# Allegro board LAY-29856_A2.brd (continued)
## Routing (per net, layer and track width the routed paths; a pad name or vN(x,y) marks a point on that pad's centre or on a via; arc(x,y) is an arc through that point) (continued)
P3V3_SDA: length 105.7
  TOP w0.152: v1(136.65,54.86) 136.49,55.02 U23.1 ; U24.1 136.49,50.32 v1(136.65,50.16) ; U21.1 136.49,64.42 v1(136.65,64.26)
  TOP w0.203: v1(136.64,58.88) 136.48,59.04 U22.1 ; U15.1 117.86,63.12 C153.1
  TOP w0.279: C154.1 124.33,68.83 U17.5 ; U16.11 119.77,76.82 v1(119.44,77.15) ; v1(121.41,79.5) 121.69,79.23 U16.7
  TOP w0.305: 125.79,78.98 125.55,78.74 124.84,78.74 124.69,78.59 U16.1
  TOP w0.381: J29.1 C163.1 105.92,87.63 106.3,88.01 112.39,88.01 112.77,87.63 R207.1 116.83,82.42 ; v1(125.98,68.07) 126.87,67.18 135,67.18 v1(135.64,66.55) ; v1(125.98,68.07) v1(125.98,70.48) ; v1(125.98,68.07) C154.1 ; v1(136.65,64.26) 136.65,64.14 R194.1 ; C156.1 121.41,79.51 v1(121.41,79.5) ; C153.1 117.35,61.59 R180.1 117.35,60.07 117.86,59.56 120.65,59.56 121.54,60.45 121.54,62.1 122.05,62.1 122.43,62.48 122.43,66.68 v1(122.18,66.93) R185.1 ; R206.1 v1(137.03,47.75) ; 116.83,82.42 C155.1 v1(120.4,82.42) 120.52,82.42 R181.1 ; 116.83,82.42 116.83,79.76 v1(119.44,77.15) ; v1(117.22,75.95) 116.72,75.44 R182.1 ; R209.1 132.59,77.72 v1(132.59,77.72) ; R202.1 v1(137.03,52.45) ; 127.64,75.69 v1(127.64,74.68) ; 125.79,78.98 126.24,79.43 v1(126.24,80.26) C157.1
  BOTTOM w0.381: v1(135.64,66.55) 135.64,65.28 v1(136.65,64.26) 137.92,62.99 137.92,60.16 v1(136.64,58.88) 136.65,58.87 v1(136.65,54.86) 136.65,52.83 v1(137.03,52.45) 136.65,52.07 v1(136.65,50.16) 137.03,49.78 v1(137.03,47.75) ; v1(122.18,66.93) 124.84,66.93 v1(125.98,68.07) ; v1(119.44,77.15) 118.43,77.15 v1(117.22,75.95)
P5V0_SDA_USB_CONN_VBUS: length 6.2
  TOP w0.381: L11.1 127.24,81.97 U18.1 127.24,83.96 126.75,84.45 124.84,84.45 124.49,84.81 J23.1
P5V_SDA: length 51.8
  TOP w0.254: U25.B2 U25.B1 U25.C1
  TOP w0.279: U16.6 122.19,79.49 v1(122.17,79.5)
  TOP w0.381: R212.1 C164.1 ; 130.05,81.03 130.43,80.64 131.44,80.64 133.22,78.87 v1(133.22,78.49) ; 130.05,81.03 129.67,80.64 127.76,80.64 v1(127,79.88) ; 130.05,81.03 C159.1 L11.2 ; v1(128.14,78.87) 128.26,78.99 R200.1 ; R195.1 116.2,67.44 114.55,69.09 114.55,72.9 113.46,73.99 113.46,78.79 v1(113.54,78.87) ; R208.1 132.46,72.64
  BOTTOM w0.381: v1(128.14,78.87) 128.02,78.87 v1(127,79.88) 125.73,78.61 123.7,78.61 122.81,79.5 v1(122.17,79.5) 122.17,79.25 121.79,78.87 v1(113.54,78.87) ; v1(133.22,78.49) 133.22,77.09 132.33,76.2 v1(132.33,74.3)
P5V_SDA_S: length 172.2
  TOP w0.381: J1.5 35.69,16.38 46.35,5.71 62.61,5.71 66.67,1.65 121.28,1.65 125.22,5.59 125.22,25.15 135.51,35.43 135.51,47.24 v1(135,47.75) ; R208.2 R210.2 v1(133.48,69.85)
  BOTTOM w0.381: v1(133.48,69.85) 134.87,68.45 134.87,63.88 136.53,62.23 136.53,61.21 135,59.69 v1(135,47.75)
VDD_COIN_3V: length 3.9
  TOP w0.381: R17.1 30.99,49.82 D6.A J7.2
VDD_HIGH_IN_3V3: length 7.6
  TOP w0.381: R14.1 42.04,33.66 J5.1 39.88,33.15 C56.1 38.86,34.17 R49.2 R45.2
VDD_HIGH_IN_MCU: length 10.7
  TOP w0.305: U1.69 46.34,41.39 45.11,40.16
  TOP w0.381: J5.2 42.04,35.18 R14.2 43.95,35.19 C19.1 43.95,37.71 C20.1 45.11,38.89 45.11,40.16
VDD_SNVS_3V3: length 36
  TOP w0.305: v1(30.86,42.29) 20.32,42.29 17.78,39.75 C60.1 17.21,38.29 U5.4
  TOP w0.381: v1(29.84,49.53) 29.84,48.43 D4.A 30.52,46.95 C48.1 30.99,46.48 R37.2 R36.2 v1(29.97,46.35) ; R25.1 v1(28.57,56.64)
  BOTTOM w0.381: v1(29.97,46.35) 30.86,45.46 v1(30.86,42.29) ; v1(28.57,56.64) 28.57,53.09 29.84,51.82 v1(29.84,49.53)
VDD_SNVS_IN: length 19.3
  TOP w0.305: U1.55 45.7,48.39 44.94,49.16
  TOP w0.381: J6.2 34.92,49.78 R16.2 37.84,49.78 C23.1 42.93,49.4 43.16,49.16 44.94,49.16 ; R26.1 v1(31.62,53.6)
  BOTTOM w0.381: v1(31.62,53.6) 31.62,52.2 33.53,50.29 J6.2
VDD_SOC_IN: length 40.8
  TOP w0.305: U1.114 67.59,42.39 v1(67.18,42.8) ; C17.1 45.85,56.64 46.1,56.39 U1.39 ; U1.31 51.66,58.14 v1(51.44,57.91) 50.29,56.77 v1(50.29,54.48) ; U1.134 67.5,52.39 v1(67.18,52.07) ; v1(55.75,39.37) 55.66,39.28 U1.86 ; v1(64.9,58.04) 64.66,58.27 U1.5 ; U1.102 63.66,38.95 v1(63.25,39.37)
  TOP w0.508: 36.27,59.74 J4.1 ; J4.1 38.15,57.86 ; J4.1 36.27,57.86 ; J4.1 38.15,59.74
  BOTTOM w0.381: C15.1 C16.1 v1(56.52,41.27) ; C15.1 v1(56.52,40.26) ; C15.1 55.75,39.38 v1(55.75,39.37) ; C10.1 v1(51.44,57.91) ; v1(67.18,42.8) 67.18,42.79 C12.1 63.87,42.79 v1(63.24,42.16) C14.1 C13.1 63.24,39.38 v1(63.25,39.37) ; v1(63,52.08) C9.1 67.18,52.08 v1(67.18,52.07) ; v1(62.87,54.23) 64.89,56.25 C8.1 64.89,58.03 v1(64.9,58.04)
  vias: v1(42.93,58.42) v1(42.93,57.66) v1(43.81,58.42) v1(43.81,57.66) v1(44.7,57.4) v1(55.37,54.48) v1(55.37,53.59) v1(56.26,54.48) v1(56.26,53.59) v1(57.15,54.48) v1(57.15,53.59)
VDD_USB_3V: length 11.1
  TOP w0.305: 39.83,43.99 42.72,43.99 43.51,44.78 45.29,44.78 45.9,45.39 U1.61
  TOP w0.381: C79.1 38.48,45.59 C80.1 39.5,44.32 39.83,43.99
VDDA_ADC_3P3_MCU: length 15.5
  TOP w0.305: U1.73 49.16,36.2
  TOP w0.381: 49.16,36.2 49.16,35.06 C6.1 C7.1 49.16,32.39 47.75,30.99 45.47,30.99 43.81,29.34 R12.2 42.04,28.45 J3.2
VDDA_ADC_3V3: length 6.7
  TOP w0.381: R35.2 38.73,27.69 C47.1 40.39,27.56 J3.1 42.04,26.92 R12.1
AUD_INT: length 60.4
  TOP w0.127: R84.1 59.44,9.02 v1(59.69,9.27) ; v1(65.53,15.62) 64.9,15.62 62.87,17.65 54.86,17.65 54.61,17.91 46.23,17.91 45.21,18.92 45.21,29.21 46.1,30.1 51.05,30.1 v1(51.31,30.35) ; R83.1 v1(55.5,33.53) 55.88,33.91 55.88,34.89 56.01,35.02 56.48,35.02 56.66,35.2 56.66,35.39 56.54,35.52 56.26,35.52 56.13,35.65 56.13,35.9 56.26,36.03 56.54,36.03 56.66,36.15 U1.88
  BOTTOM w0.127: v1(65.53,15.62) 65.53,15.11 v1(59.69,9.27) ; v1(51.31,30.35) 52.32,30.35 v1(55.5,33.53)
CAN1_H: length 13.2
  TOP w0.107: J10.1 50.28,84.47 C88.2 50.29,84.44 D11.2 48.75,82.8 R77.1 47.99,81.03 47.88,80.92 47.88,80.23 FL1.1 47.99,79.11 47.87,78.99 47.87,77.6 47.88,77.59 47.88,77.59 R76.2
CAN1_L: length 13.2
  TOP w0.107: R79.2 47.24,77.22 47.61,77.59 47.61,79 47.51,79.11 FL1.2 47.62,80.23 47.62,80.92 47.52,81.03 R78.2 46.75,82.67 46.8,82.72 D11.1 46.8,82.86 C90.1 45.2,84.47 J10.3
CAN1_RX: length 17.4
  TOP w0.127: U9.4 46.35,68.96 46.61,68.71 47.24,68.71 48.51,67.44 52.07,67.44 53.59,65.91 53.59,63.63 51.16,61.19 U1.32
CAN1_TX: length 27.3
  TOP w0.127: U9.1 41.66,72.77 41.27,72.39 41.27,69.98 43.05,68.2 47.12,68.2 48.26,67.06 51.82,67.06 53.09,65.79 53.09,63.75 50.66,61.33 U1.33
CAN_STBY: length 52.6
  TOP w0.127: U1.76 50.66,39 49.83,39.83 49.83,53.54 49.43,53.95 49.43,57.63 47.5,59.56 v1(47.5,59.94) ; R74.1 54.1,69.86 v1(54.1,64.77) ; v1(56.26,66.55) 57.15,67.44 57.15,73.79 57.91,74.55 58.55,74.55 58.93,74.93 60.46,74.93 R161.2
  BOTTOM w0.127: v1(56.26,66.55) 54.48,64.77 v1(54.1,64.77) 54.1,63.37 53.29,62.56 51.18,62.56 50.6,61.98 49.53,61.98 v1(47.5,59.94)
CAN_VIO_3V3: length 4.2
  TOP w0.381: C87.1 52.58,69.98 R73.1 ; C87.1 R72.1 ; C87.1 U9.5
DC_5V_IN: length 13.9
  TOP w0.305: 11.3,10.29 8.64,12.95 R6.1
  TOP w0.762: J2.1 13.08,8.92 ; J2.1 13.08,4.55 ; J2.1 12.13,6.73 ; J2.1 14.03,6.73
DCDC_3V3: length 285
  TOP w0.152: v1(135.76,50.16) 135.79,50.2 U24.6 ; U21.6 135.79,64.41 135.64,64.26 v1(135.64,64.26) ; 118.55,64.71 118.85,64.41 U15.8 ; U23.6 135.79,54.89 v1(135.76,54.86)
  TOP w0.203: v1(135.76,58.93) 135.81,58.97 U22.8
  TOP w0.254: U27.A1 23.88,58.93 C171.1
  TOP w0.305: R66.1 12.19,49.91 R64.1 ; U11.17 82.7,19.91 81.79,20.83 C134.1
  TOP w0.381: R132.2 78.61,19.68 v1(78.61,20.69) R136.2 ; R115.1 v1(78.61,16.26) ; R149.1 v1(130.17,46.22) ; R148.1 v1(128.14,34.42) ; D12.A v1(111.12,48.86) 110.74,48.47 R144.1 ; 72.9,8.13 v1(72.9,26.16) 72.9,26.29 71.25,27.94 69.85,27.94 68.71,29.08 65.41,29.08 62.1,32.38 R80.1 ; R197.1 v1(127.76,62.61) R192.1 ; v1(32.51,45.59) R37.1 ; R114.1 R119.2 87,24.95 86.61,25.33 85.54,25.33 84.96,25.91 84.2,25.91 83.95,25.65 v1(83.95,25.53) R123.2 83.81,24.5 R124.2 ; R114.1 88.01,25.02 v1(88.27,25.27) ; R114.1 R113.1 v1(89.03,25.27) ; v1(23.11,56.77) 21.34,56.77 R28.1 ; R47.1 v1(51.68,66.43) 51.56,66.55 47.88,66.55 46.74,67.69 42.93,67.69 39.75,70.87 v1(35.69,70.87) ; R239.1 54.36,85.72 53.72,85.09 53.72,81.92 54.1,81.53 v1(54.1,71.5) ; L9.1 92.58,10.93 ; v1(82.55,21.34) C134.1 81.66,21.34 80.78,22.22 R130.2 ; 118.55,64.71 118.24,65.02 118.24,65.41 C152.1 v1(117.22,64.52) 117.22,63.89 R186.1 ; v1(78.74,10.03) 78.36,10.41 R128.2 ; R146.1 v1(124.84,47.62) ; R64.1 12.19,47.88 12.83,47.24 12.83,46.99 14.22,45.59 v1(21.59,45.59) ; R45.1 36.07,34.92 ; v1(134.87,46.48) v1(134.87,41.91) ; C171.1 v1(24.77,59.69) v1(26.8,59.69) 27.55,59.69 R19.1 ; R72.2 v1(53.33,67.18) ; v1(81.28,10.16) 81.41,10.29 R129.2 ; 85.47,7.62 R118.2 ; v1(91.44,25.27) 92.08,24.64 R108.1 ; R359.1 25.27,67.82 v1(25.78,67.31) 27.43,65.66 v1(27.43,61.21) ; R110.1 v1(91.06,18.03) ; J14.1 v1(117.47,18.68) ; v1(129.03,58.93) v1(135.76,58.93) ; R15.1 v1(73.41,36.7) ; R147.1 v1(125.22,34.42) ; R109.1 v1(91.06,19.18)
  TOP w0.508: 32,34.87 J8.1 ; J8.1 32.94,35.81 ; J8.1 31.06,35.81 ; J8.1 32,36.75
  BOTTOM w0.381: v1(25.78,67.31) 29.08,67.31 32.64,70.87 v1(35.69,70.87) ; v1(26.8,59.69) 27.43,60.33 v1(27.43,61.21) ; v1(127.76,62.61) v1(124.59,62.61) ; v1(111.12,48.86) 111.12,51.44 ; v1(81.28,10.16) 80.77,10.67 79.25,10.67 78.74,10.16 v1(78.74,10.03) v1(78.74,8.26) ; v1(32.51,45.59) 32.51,43.69 33.02,43.18 v1(33.02,40.39) ; v1(124.59,57.78) 127.89,57.78 v1(129.03,58.93) ; v1(73.41,36.7) 73.28,36.58 73.28,26.54 v1(72.9,26.16) ; v1(78.61,16.26) 79.25,16.9 79.25,20.06 v1(78.61,20.69) 79.25,21.34 v1(82.55,21.34) 83.19,21.97 83.19,24 83.95,24.77 v1(83.95,25.53) ; v1(125.22,34.42) 126.41,33.23 ; R142.1 57.02,70.48 56.01,71.5 v1(54.1,71.5) 54.1,67.95 v1(53.33,67.18) 52.58,66.43 v1(51.68,66.43) ; v1(117.22,64.52) 109.22,64.52 ; v1(134.87,46.48) 135.64,47.24 135.64,50.04 v1(135.76,50.16) v1(135.76,54.86) v1(135.76,58.93) 135.76,59.18 137.26,60.68 137.26,62.64 v1(135.64,64.26) ; v1(117.47,18.68) v1(120.52,18.68)
  BOTTOM w0.508: 107.13,75.24 J20.4 ; J20.4 108.13,76.25 ; J20.4 107.13,77.25 ; J20.4 106.13,76.25 ; J16.2 132.13,38.48 ; J16.2 131.06,39.55 ; J16.2 130,38.48 ; J16.2 131.06,37.41 ; J19.8 119.82,27.99 ; J19.8 118.81,28.99 ; J19.8 117.81,27.99 ; J19.8 118.81,26.98 ; 112.21,75.24 J20.2 ; J20.2 113.21,76.25 ; J20.2 111.21,76.25 ; J20.2 112.21,77.25
  vias: v1(26.29,39.88) v1(26.92,38.99) v1(27.43,39.88) v1(27.94,38.99) v1(28.45,39.88) v1(90.3,15.75) v1(90.3,14.99) v1(90.93,14.99) v1(91.82,26.04) v1(92.71,26.04) v1(93.6,26.04) v1(95.38,22.86) v1(95.38,22.1) v1(96.27,22.86) v1(96.27,22.1) v1(120.4,25.15) v1(120.4,24.13) v1(121.54,25.15) v1(121.54,24.13) v1(122.81,25.15) v1(122.81,24.13) v1(123.7,51.69) v1(123.83,52.45) v1(124.59,51.82)
DCDC_3V3_PG: length 41.8
  TOP w0.305: U6.3 19.12,63.19 18.54,62.61 18.54,52.7 v1(18.8,52.45) ; U4.1 21.76,29.76 21.34,29.34 C57.1 C58.1 18.54,29.34 TP9.1 15.11,32.77 15.11,38.61 v1(18.41,41.91)
  BOTTOM w0.305: v1(18.8,52.45) 19.05,52.2 19.05,42.55 v1(18.41,41.91)
DCDC_OUT: length 3.8
  TOP w0.508: 37.21,60.4 J4.2 ; J4.2 37.21,62.28 ; J4.2 36.27,61.34 ; J4.2 38.15,61.34
ENET_B-CAST-OFF: length 4.5
  TOP w0.127: R136.1 80.51,19.95 TP14.1 81.41,19.94 82.43,18.91 U11.19
ENET_CONFIG0: length 9.5
  TOP w0.127: U11.28 85.6,14.86 84.45,13.72 81.41,13.72 R125.1 78.49,11.68 R128.1
ENET_CONFIG1: length 8.4
  TOP w0.127: U11.29 86.1,14.6 84.84,13.34 82.42,13.34 81.41,12.32 R129.1 R126.1
ENET_CRS_DV: length 48
  TOP w0.127: U1.97 61.16,37 65.81,32.36 71.63,32.36 76.58,27.41 76.58,25.59 76.71,25.46 77.34,25.46 77.47,25.34 77.47,25.08 77.34,24.95 76.71,24.95 76.58,24.83 76.58,24.57 76.71,24.45 77.34,24.45 77.47,24.32 77.47,24.07 77.34,23.94 76.71,23.94 76.58,23.81 76.58,23.56 76.71,23.43 77.34,23.43 77.47,23.3 77.47,23.05 77.34,22.92 76.71,22.92 76.58,22.8 76.58,22.54 76.71,22.41 77.34,22.41 77.47,22.29 77.47,22.03 77.34,21.91 76.71,21.91 76.58,21.78 76.58,21.59 76.71,21.46 77.32,21.46 77.45,21.34 77.45,20.7 77.58,20.57 77.83,20.57 77.96,20.7 77.96,24.36 78.09,24.49 78.36,24.49 78.48,24.36 78.48,21.6 78.61,21.47 R127.1 R130.1 v1(81.16,20.7) 82.45,19.41 U11.18
  BOTTOM w0.127: v1(81.16,20.7) 81.41,20.45 R169.2
ENET_INT: length 67.2
  TOP w0.127: R166.2 98.55,24.38 v1(98.3,24.13) ; U1.84 54.66,36.7 54.79,36.58 v1(55.24,36.58) ; U11.21 82.55,17.91 v1(82.3,17.65) 81.65,17.01 R137.1 R115.2 78.01,17.01 77.88,16.88 77.88,16.21 77.75,16.08 77.5,16.08 77.37,16.21 77.37,16.88 77.25,17.01 76.99,17.01 76.87,16.88 76.87,16.21 76.74,16.08 76.48,16.08 76.36,16.21 76.36,16.88 76.23,17.01 75.57,17.01 75.32,17.26 75.32,26.95 71.12,31.16 65.87,31.16 61.09,35.94 v1(60.71,35.94)
  BOTTOM w0.127: v1(60.71,35.94) 60.07,36.58 v1(55.24,36.58) ; v1(98.3,24.13) 92.84,24.13 89.03,20.32 84.12,20.32 83.26,19.46 83.26,18.62 v1(82.3,17.65)
ENET_LED0/NWAYEN: length 43.8
  TOP w0.127: J14.2 106.86,16.84 103.5,20.19 v1(98.04,20.19) ; R133.1 v1(82.42,12.45) 82.8,12.83 85.09,12.83 86.6,14.34 U11.30
  BOTTOM w0.127: v1(98.04,20.19) 97.92,20.19 90.93,13.21 83.19,13.21 v1(82.42,12.45)
ENET_LED1/SPEED: length 39.7
  TOP w0.127: U11.31 87.1,13.95 85.47,12.32 v1(84.08,12.32) R134.1 ; v1(94.36,13.21) 103.63,13.21 106.81,10.03 109.09,10.03 111.83,7.29 J14.11
  BOTTOM w0.127: v1(84.08,12.32) 84.16,12.24 93.4,12.24 v1(94.36,13.21)
ENET_MDC: length 36.4
  TOP w0.127: U11.12 86.1,22.47 v1(86.61,22.99) 87.24,22.99 R114.2 ; v1(85.6,33.91) 81.92,37.59 76.78,37.59 73.1,41.27 70.96,41.27 69.34,42.89 U1.115
  BOTTOM w0.127: v1(86.61,22.99) 86.61,26.04 85.6,27.05 v1(85.6,33.91)
ENET_MDIO: length 39.6
  TOP w0.127: v1(88.01,33.91) 86.36,33.91 82.17,38.1 76.73,38.1 73.18,41.66 71.08,41.66 69.34,43.39 U1.116 ; R113.2 88.39,23.11 87.88,23.11 87.25,22.48 v1(87.12,22.48) 86.6,21.96 U11.11
  BOTTOM w0.127: v1(88.01,33.91) 88.01,27.05 87.12,26.16 v1(87.12,22.48)
ENET_PHYAD0: length 4.3
  TOP w0.127: U11.13 85.6,23.38 R122.1 R119.1
ENET_PHYAD1: length 4.3
  TOP w0.127: U11.14 85.1,23.62 R120.1 84.08,23.76 R123.1
ENET_RST: length 94.6
  TOP w0.127: U1.107 66.16,37.22 v1(66.8,36.58) ; J16.13 114.55,39.75 v1(114.55,35.81) ; v1(69.98,29.72) 70.62,29.72 73.95,26.39 73.95,14.06 78.49,9.53 83.82,9.53 v1(84.45,10.16) R116.1 ; v1(115.06,31.24) 115.06,27.18 110.11,22.23 101.47,22.23 v1(101.35,22.1)
  BOTTOM w0.127: v1(115.06,31.24) 114.55,31.75 v1(114.55,35.81) ; v1(101.35,22.1) 94.87,15.62 94.87,13.08 93.65,11.86 86.16,11.86 v1(84.45,10.16) ; v1(69.98,29.72) 69.98,33.4 v1(66.8,36.58)
ENET_RXD0: length 47.8
  TOP w0.127: U11.16 84.1,21.56 v1(83.95,21.72) 82.55,23.11 81.41,23.11 R135.1 80.26,23.76 80.14,23.63 80.14,22.99 80.01,22.86 79.76,22.86 79.63,22.99 79.63,23.29 79.5,23.41 78.99,23.41 78.87,23.54 78.87,23.77 78.99,23.9 79.38,23.9 79.5,24.02 79.5,24.26 79.38,24.38 78.99,24.38 78.87,24.51 78.87,24.77 78.99,24.89 79.64,24.89 79.77,25.02 79.77,25.27 79.89,25.4 81.1,25.4 81.23,25.53 81.23,25.78 81.1,25.91 79.53,25.91 79.4,25.78 79.4,25.4 79.28,25.27 79.02,25.27 78.9,25.4 78.9,25.78 78.77,25.91 78.51,25.91 78.39,25.78 78.39,25.02 78.26,24.89 78.01,24.89 77.88,25.02 77.88,25.78 77.75,25.91 77.34,25.91 77.09,26.16 77.09,28.07 76.9,28.26 76.72,28.26 76.53,28.07 76.35,28.07 76.17,28.25 76.17,28.43 76.36,28.61 76.36,28.79 76.18,28.97 76,28.97 75.82,28.79 75.64,28.79 75.46,28.97 75.46,29.15 75.64,29.33 75.64,29.51 75.46,29.69 75.28,29.69 75.1,29.51 74.92,29.51 74.74,29.69 74.74,29.87 74.92,30.05 74.92,30.23 74.74,30.41 74.56,30.41 74.38,30.23 74.2,30.23 74.02,30.4 74.02,30.58 74.2,30.77 74.2,30.95 74.03,31.13 73.85,31.13 73.66,30.94 73.48,30.94 73.3,31.12 73.3,31.3 73.49,31.49 73.49,31.67 73.31,31.85 73.13,31.85 72.94,31.66 72.76,31.66 72.58,31.84 72.58,32.02 72.77,32.21 72.77,32.39 72.59,32.57 72.41,32.57 72.22,32.38 72.04,32.38 71.76,32.66 65.93,32.66 61.66,36.94 U1.98
  BOTTOM w0.127: R172.2 v1(83.95,21.72)
ENET_RXD1: length 47.3
  TOP w0.127: U11.15 84.6,21.82 83.06,23.37 R124.1 R121.1 81.66,23.76 81.53,23.88 81.53,25.29 R155.2 81.57,26.29 77.6,26.29 77.47,26.42 77.47,28.12 77.06,28.53 77.06,28.71 77.42,29.08 77.42,29.26 77.24,29.44 77.06,29.44 76.7,29.07 76.52,29.07 76.34,29.25 76.34,29.43 77.09,30.18 77.09,30.36 76.91,30.54 76.73,30.54 75.98,29.79 75.8,29.79 75.62,29.97 75.62,30.15 76.37,30.9 76.37,31.08 76.19,31.25 76.01,31.25 75.26,30.51 75.08,30.51 74.9,30.69 74.9,30.87 75.9,31.87 75.9,32.05 75.72,32.23 75.54,32.23 74.54,31.23 74.36,31.23 74.18,31.41 74.18,31.59 75.18,32.59 75.18,32.77 75,32.95 74.5,32.95 74.3,32.74 74.3,32.42 73.82,31.94 73.64,31.94 73.46,32.12 73.46,32.3 73.77,32.61 73.77,32.79 73.59,32.97 73.41,32.97 73.1,32.66 72.92,32.66 72.62,32.97 66.06,32.97 62.16,36.87 U1.99
ENET_RXER: length 48.5
  TOP w0.127: U11.20 v1(82.29,18.41) 81.78,18.41 81.65,18.28 81.65,17.55 81.52,17.42 81.27,17.42 81.14,17.55 81.14,17.91 81.02,18.03 80.4,18.03 R131.1 79.51,18.04 R132.1 78.99,17.53 78.17,17.53 78.04,17.65 78.04,19.94 77.91,20.07 77.66,20.07 77.53,19.94 77.53,18.16 77.4,18.03 76.33,18.03 76.2,18.16 76.2,18.41 76.33,18.54 76.96,18.54 77.09,18.67 77.09,18.92 76.96,19.05 76.33,19.05 76.2,19.18 76.2,19.43 76.33,19.56 76.96,19.56 77.09,19.69 77.09,19.94 76.96,20.07 76.35,20.07 76.21,20.21 76.21,20.41 76.34,20.54 76.96,20.54 77.09,20.67 77.09,20.92 76.96,21.05 76.34,21.05 76.21,21.17 76.21,27.35 71.51,32.05 65.68,32.05 61.29,36.45 60.79,36.45 60.66,36.58 U1.96
  BOTTOM w0.127: R170.2 81.92,18.78 v1(82.29,18.41)
ENET_RXM: length 32.2
  TOP w0.107: J14.8 112.05,10.53 111.95,10.64 111.95,10.81 111.84,10.92 107.97,10.92 107.38,11.51 107.23,11.51 107.07,11.35 106.92,11.35 106.77,11.5 106.77,11.67 106.91,11.82 106.91,11.97 106.76,12.12 106.61,12.12 106.45,11.96 106.3,11.96 106.16,12.1 106.16,12.28 106.31,12.43 106.31,12.58 106.06,12.83 104.92,12.83 104.14,13.6 104.14,14.11 103.95,14.3 U12.3 102.14,14.3 101.33,15.11 96.66,15.11 96.03,15.75 93.85,15.75 C133.1 93.09,15.75 92.58,15.75 R111.2 91.57,15.75 91.19,15.75 90.3,16.64 90.3,17.41 89.68,18.03 89,18.03 88.88,17.91 U11.4
ENET_RXP: length 32.2
  TOP w0.107: J14.7 112.05,11.55 111.95,11.45 111.95,11.28 111.84,11.17 108.08,11.17 106.17,13.09 105.02,13.09 104.4,13.71 104.4,14.22 104.01,14.6 104.01,15.6 103.43,16.18 U12.1 102.14,16.18 101.34,15.37 96.77,15.37 96.14,16 93.85,16 C132.1 93.09,16 92.58,16 R110.2 91.57,16 91.3,16 90.56,16.74 90.56,17.52 89.79,18.29 89,18.29 88.88,18.41 U11.5
ENET_TX_CLK: length 47.3
  TOP w0.127: U11.9 87.6,21.18 88.01,21.59 89.41,21.59 TP16.1 90.81,22.99 90.81,26.42 90.55,26.67 77.98,26.67 77.85,26.8 77.85,29.08 77.98,29.21 78.61,29.21 78.74,29.34 78.74,29.85 78.55,30.04 78.37,30.04 77.91,29.58 77.73,29.58 77.55,29.76 77.55,29.94 78.01,30.4 78.01,30.58 77.83,30.76 77.65,30.76 77.57,30.68 77.39,30.68 77.21,30.86 77.21,31.04 77.29,31.12 77.29,31.3 77.11,31.48 76.93,31.48 76.85,31.4 76.67,31.4 76.49,31.58 76.49,31.76 76.57,31.84 76.57,32.02 75.24,33.35 66.22,33.35 62.66,36.91 U1.100
ENET_TXD0: length 67.6
  TOP w0.127: R164.2 v1(97.54,23.24) ; U1.94 59.66,35.59 60.71,34.54 61.51,34.54 65.59,30.47 70.84,30.47 74.64,26.67 74.64,15.87 74.8,15.71 75.31,15.71 75.44,15.58 75.44,15.33 75.31,15.2 74.8,15.2 74.68,15.07 74.68,14.61 75.06,14.22 75.56,14.22 75.71,14.37 75.71,14.86 75.84,14.99 76.09,14.99 76.22,14.86 76.22,13.32 76.33,13.21 76.58,13.21 76.71,13.34 76.71,13.91 76.83,14.03 80.71,14.03 TP15.1 82.3,15.62 v1(82.3,16) 82.7,16.41 U11.24
  BOTTOM w0.127: v1(82.3,16) 84.45,18.16 84.45,18.8 85.22,19.56 89.49,19.56 93.3,23.37 97.41,23.37 v1(97.54,23.24)
ENET_TXD1: length 48.3
  TOP w0.127: U1.93 59.16,35.58 60.83,33.91 61.72,33.91 65.46,30.17 70.71,30.17 74.33,26.54 74.33,14.31 75.95,12.7 77.14,12.7 77.27,12.83 77.27,13.21 77.4,13.34 77.65,13.34 77.78,13.21 77.78,12.83 77.91,12.7 78.16,12.7 78.29,12.83 78.29,13.08 78.41,13.21 78.67,13.21 78.8,13.08 78.8,12.83 78.92,12.7 79.88,12.7 81.41,14.22 83.44,14.22 v1(83.57,14.35) 84.1,14.89 U11.25
  BOTTOM w0.127: v1(83.57,14.35) 84.33,14.35 R168.2
ENET_TXEN: length 49.6
  TOP w0.127: U1.95 60.16,35.72 60.71,35.18 61.31,35.18 65.71,30.78 70.96,30.78 74.94,26.8 74.94,16.75 76.2,15.49 76.61,15.49 76.74,15.37 76.74,14.61 76.87,14.48 77.12,14.48 77.25,14.61 77.25,15.37 77.37,15.49 77.63,15.49 77.76,15.37 77.76,14.61 77.88,14.48 78.14,14.48 78.26,14.61 78.26,15.37 78.39,15.49 78.64,15.49 78.77,15.37 78.77,14.61 78.9,14.48 79.15,14.48 79.28,14.61 79.28,15.39 79.41,15.52 79.66,15.52 79.79,15.39 79.79,14.61 79.91,14.48 80.17,14.48 80.3,14.61 80.3,15.37 80.42,15.49 81.03,15.49 v1(82.3,16.76) 82.44,16.91 U11.23
  BOTTOM w0.127: v1(82.3,16.76) 82.3,16.9 R171.2
ENET_TXM: length 33.2
  TOP w0.107: U11.6 88.88,18.91 89,19.03 89.64,19.03 90.17,19.56 90.17,20.59 90.79,21.21 91.57,21.21 R109.2 92.58,21.21 93.09,21.21 C131.1 93.85,21.21 94.12,21.21 97.68,17.65 103.77,17.65 104.13,17.29 104.13,16.28 104.52,15.89 104.52,14.93 105.15,14.3 U12.4 106.4,14.3 106.68,14.58 106.68,14.76 106.92,15 111.84,15 111.95,14.89 111.95,14.72 112.05,14.61 J14.4
ENET_TXP: length 33.1
  TOP w0.107: J14.3 112.05,15.63 111.95,15.53 111.95,15.36 111.84,15.25 107.17,15.25 106.25,16.18 U12.6 104.6,16.18 104.39,16.38 104.39,17.4 103.88,17.91 103.42,17.91 103.31,18.02 103.31,18.21 103.2,18.31 102.99,18.31 102.88,18.21 102.88,18.02 102.78,17.91 102.56,17.91 102.46,18.02 102.46,18.21 102.35,18.31 102.14,18.31 102.03,18.21 102.03,18.02 101.92,17.91 101.2,17.91 101.08,18.03 100.84,18.03 100.72,17.91 97.78,17.91 94.23,21.47 93.85,21.47 C130.1 93.09,21.47 92.58,21.47 R108.2 91.57,21.47 90.68,21.47 89.91,20.7 89.91,19.67 89.54,19.29 89,19.29 88.88,19.41 U11.7
FLASH_3V3: length 18.8
  TOP w0.381: v1(69.34,70.48) R143.1 ; U13.8 v1(59.87,67.56)
  BOTTOM w0.381: v1(59.87,67.56) 59.87,67.61 59.81,67.67 C142.1 59.94,68.59 C143.1 ; 61.09,69.47 C143.1 ; C143.1 59.81,69.6 R142.2 59.81,72.52 60.19,72.9 66.93,72.9 v1(69.34,70.48)
FLEXSPI_CLK: length 19.6
  TOP w0.127: U13.6 61.37,71.12 61.5,70.99 61.5,70.43 61.62,70.31 61.88,70.31 62,70.43 62,70.99 62.13,71.12 62.35,71.12 63.12,70.35 63.12,68.2 57.66,62.74 57.02,62.74 55.32,61.04 55.32,60.4 55.16,60.24 U1.24
FLEXSPI_D0_A: length 19.6
  TOP w0.127: U13.5 62.36,72.39 63.5,71.25 63.5,67.94 57.91,62.36 57.28,62.36 55.75,60.83 55.75,60.07 55.66,59.98 U1.23
FLEXSPI_D1_A: length 19.5
  TOP w0.127: U13.2 65.02,69.85 64.9,69.98 64.9,70.74 64.77,70.87 64.45,70.87 64.33,70.74 64.33,69.41 64.45,69.28 64.77,69.28 64.9,69.15 64.9,68.9 64.77,68.77 64.45,68.77 64.33,68.65 64.33,67.75 58.17,61.59 57.53,61.59 56.66,60.73 U1.21
FLEXSPI_D2_A: length 19.6
  TOP w0.127: U13.3 65.72,71.12 65.53,71.31 65.53,71.5 65.15,71.88 64.26,71.88 63.88,71.5 63.88,67.82 58.04,61.98 57.4,61.98 56.16,60.73 U1.22
FLEXSPI_D3_A: length 20.7
  TOP w0.127: U13.7 61.4,69.85 61.52,69.72 61.52,69.22 61.65,69.09 61.9,69.09 62.03,69.22 62.03,69.72 62.16,69.85 62.48,69.85 62.61,69.72 v1(62.61,68.71) 62.61,68.33 62.39,68.11 62.21,68.11 61.69,68.62 61.51,68.62 61.33,68.45 61.33,68.27 61.85,67.75 61.85,67.57 57.45,63.16 56.81,63.16 54.94,61.29 54.94,60.65 54.66,60.38 U1.25
  BOTTOM w0.127: v1(62.61,68.71) 62.61,68.96 R313.2
FLEXSPI_SS0: length 19.6
  TOP w0.127: U1.19 57.66,60.15 57.3,60.51 57.3,60.91 57.61,61.21 58.29,61.21 64.9,67.82 68.71,67.82 69.34,68.45 R143.2 68.59,68.84 68.33,68.58 U13.1
GPIO_AD_B0_05: length 75.1
  TOP w0.127: J16.3 127.25,39.75 127.25,36.2 126.63,35.57 R148.2 125.99,33.78 103.89,33.78 102.87,34.8 91.82,34.8 89.03,32 84.85,32 81.29,35.56 80.01,35.56 79.76,35.31 R160.2 79.38,34.8 78.36,35.81 76.33,35.81 75.82,36.32 73.91,36.32 73.41,35.81 71.62,35.81 D5.C 67.68,36.69 67.06,36.07 66.62,36.07 65.66,37.03 U1.106
GPIO_AD_B0_06: length 106.4
  TOP w0.127: J26.2 130.17,61.09 R197.2 ; v1(126.87,58.55) 127.13,58.29 127.13,51.43 133.35,45.21 133.35,37.29 129.33,33.27 103.38,33.27 102.49,34.16 91.82,34.16 89.28,31.62 81.03,31.62 79.76,32.89 R162.2 77.98,35.43 76.2,35.43 75.69,35.94 74.04,35.94 73.53,35.43 71.37,35.43 70.99,35.81 70.23,35.81 69.72,36.32 67.82,36.32 67.26,35.76 66.47,35.76 65.16,37.07 U1.105
  BOTTOM w0.127: J26.2 127.64,58.55 v1(126.87,58.55)
GPIO_AD_B0_07: length 115.2
  TOP w0.127: v1(90.17,31.75) 92.08,33.66 102.23,33.66 103,32.89 129.67,32.89 133.86,37.08 133.86,45.34 127.64,51.56 127.64,58.67 125.48,60.83 v1(125.48,63.88) ; J25.2 130.17,65.79 127.77,65.79 R192.2 v1(127,65.78) ; v1(90.17,30.48) 89.79,30.86 80.64,30.86 76.77,34.72 70.38,34.72 69.42,35.69 68.46,35.69 68.33,35.56 R156.2 67.69,35.18 67.67,35.15 65.56,35.15 65.02,35.69 65.02,35.94 64.77,36.2 64.01,36.2 63.16,37.04 U1.101
  BOTTOM w0.127: v1(90.17,31.75) v1(90.17,30.48) ; v1(127,65.78) 125.48,64.26 v1(125.48,63.88)
GPIO_AD_B1_07: length 142.5
  TOP w0.127: v1(14.35,46.35) 14.99,46.35 15.49,46.86 15.49,51.05 14.86,51.69 14.86,52.7 13.97,53.59 v1(13.97,61.59) ; v1(65.53,35.94) 66.01,35.46 67.46,35.46 68,35.99 69.55,35.99 70.1,35.43 70.87,35.43 71.25,35.05 74.05,35.05 R167.2 ; v1(51.69,34.92) 51.05,34.29 51.05,33.53 48.01,30.48 45.82,30.48 44.7,29.36 v1(44.7,18.29) ; v1(21.34,21.34) 15.75,21.34 10.67,26.42 10.67,40.36 v1(11.33,41.02) ; v1(19.3,61.59) 19.81,62.1 21.97,62.1 22.35,61.72 23.11,61.72 24,60.83 24.9,60.83 R55.1 25.13,61.07 Q8.2 ; v1(36.58,18.29) 36.58,21.21 31.37,26.42 26.42,26.42 v1(25.78,25.78) ; v1(54.74,35.56) 54.74,35.94 54.23,36.45 54.23,36.89 54.16,36.96 U1.83
  BOTTOM w0.127: v1(65.53,35.94) 64.64,35.05 60.07,35.05 59.56,35.56 v1(54.74,35.56) 54.1,35.56 53.47,34.92 v1(51.69,34.92) ; v1(14.35,46.35) 14.35,45.72 12.19,43.56 12.19,41.88 v1(11.33,41.02) ; v1(19.3,61.59) v1(13.97,61.59) ; v1(44.7,18.29) v1(36.58,18.29) ; v1(21.34,21.34) v1(25.78,25.78)
GPIO_AD_B1_08: length 17.6
  TOP w0.127: R154.2 67.95,34.67 v1(66.42,34.67) ; v1(54.23,34.92) 54.23,35.69 53.66,36.25 U1.82
  BOTTOM w0.127: v1(54.23,34.92) 59.44,34.92 59.69,34.67 v1(66.42,34.67)
GPIO_AD_B1_09: length 17.2
  TOP w0.127: v1(64.52,35.69) 66.17,34.04 R153.2 ; v1(53.34,35.56) 53.09,35.81 53.09,36.04 53.16,36.12 U1.81
  BOTTOM w0.127: v1(53.34,35.56) 53.85,36.07 59.82,36.07 60.45,35.43 64.26,35.43 v1(64.52,35.69)
GPIO_AD_B1_10: length 136.1
  TOP w0.127: R69.1 12.7,52.7 12.7,79.82 19.88,87 31.05,87 40.13,77.91 v1(40.13,75.95) ; R157.2 64.9,73.79 60.07,73.79 59.69,73.41 58.93,73.41 v1(58.8,73.28) 58.29,72.77 58.29,65.53 v1(57.02,64.26) ; v1(54.48,55.37) 54.48,40.64 52.66,38.82 U1.80
  BOTTOM w0.127: v1(54.48,55.37) 53.67,56.18 51.26,56.18 50.04,57.4 50.04,59.82 51.44,61.21 53.59,61.21 56.64,64.26 v1(57.02,64.26) ; v1(58.8,73.28) 58.04,74.04 42.04,74.04 v1(40.13,75.95)
GPIO_AD_B1_11: length 148.7
  TOP w0.127: v1(40.13,75.18) 39.62,75.69 39.62,77.88 30.89,86.61 20.04,86.61 13.08,79.66 13.08,53.34 13.91,52.51 13.91,51.63 14.61,50.93 14.61,49.78 13.32,48.5 Q9.2 13.32,47.51 v1(13.72,47.12) ; v1(11.33,42.04) R68.2 ; U1.79 52.16,38.83 53.52,40.18 53.52,55.3 v1(53.59,55.37) ; R158.2 63.51,74.17 59.82,74.17 59.44,73.79 58.48,73.79 v1(58.04,73.34) 57.91,73.22 57.91,65.91 v1(57.02,65.02)
  BOTTOM w0.127: v1(11.33,42.04) 11.81,42.52 11.81,43.81 13.72,45.72 v1(13.72,47.12) ; v1(40.13,75.18) 41.66,73.66 57.72,73.66 v1(58.04,73.34) ; v1(57.02,65.02) 56.39,65.02 55.17,63.8 55.17,63.33 53.51,61.67 51.38,61.67 49.53,59.82 49.53,57.28 50.95,55.85 53.11,55.85 v1(53.59,55.37)
GPIO_AD_B1_12: length 139.8
  TOP w0.127: v1(57.02,66.55) 57.53,67.06 57.53,73.53 58.17,74.17 59.05,74.17 v1(59.31,74.42) 59.44,74.55 62.11,74.55 R159.2 ; v1(12.83,46.1) 12.83,46.22 R65.1 ; U1.78 51.66,38.84 53.21,40.39 53.21,54.86 v1(52.7,55.37) ; v1(38.61,76.96) 38.61,78.11 30.48,86.23 20.19,86.23 13.46,79.5 13.46,53.47 14.35,52.58 14.35,51.69 14.99,51.05 v1(14.99,49.4)
  BOTTOM w0.127: v1(14.99,49.4) 14.61,49.4 12.83,47.62 v1(12.83,46.1) ; v1(57.02,66.55) 54.74,64.26 54.74,63.43 53.41,62.1 51.31,62.1 49.02,59.82 49.02,57.15 50.8,55.37 v1(52.7,55.37) ; v1(59.31,74.42) 42.42,74.42 39.88,76.96 v1(38.61,76.96)
GPIO_AD_B1_14: length 57.7
  TOP w0.127: R165.2 56.13,74.29 56.13,67.56 v1(56.26,67.44) ; U10.17 53.87,28.55 53.59,28.83 53.59,31.62 R92.2 52.96,31.88 52.7,32.13 52.7,35.56 51.69,36.58 50.55,36.58 50.16,36.96 U1.75 50.16,38.99 49.5,39.65 49.5,53.37 49.12,53.75 49.12,57.43 46.74,59.82 v1(46.74,59.94)
  BOTTOM w0.127: v1(56.26,67.44) 54.48,65.66 54.23,65.66 53.59,65.02 53.59,63.53 53.03,62.97 50.93,62.97 50.32,62.36 49.15,62.36 v1(46.74,59.94)
GPIO_AD_B1_15: length 60.7
  TOP w0.127: R163.2 58.43,74.93 57.66,74.93 56.64,73.91 v1(56.64,68.96) ; U10.18 53.49,28.05 53.21,28.32 53.21,30.23 R93.2 52.07,31.88 52.32,32.13 52.32,35.31 51.56,36.07 50.42,36.07 49.66,36.82 U1.74 49.66,38.98 49.2,39.45 49.2,53.16 48.82,53.54 48.82,57.1 v1(45.97,59.94)
  BOTTOM w0.127: v1(56.64,68.96) 56.64,68.76 53.09,65.2 53.09,63.75 52.7,63.37 50.67,63.37 50.04,62.74 48.77,62.74 v1(45.97,59.94)
GPIO_EMC_16: length 38.9
  TOP w0.127: v1(87.12,59.31) 86.65,59.78 U14.23 86.65,62.19 v1(86.11,62.74) ; v1(72.26,58.5) 72.06,58.29 R299.2
  BOTTOM w0.127: v1(72.26,58.5) 72.77,59 72.77,59.94 73.28,60.45 73.28,61.21 74.93,62.87 74.93,64.52 75.06,64.64 75.3,64.64 75.43,64.52 75.43,63.63 75.55,63.5 75.81,63.5 75.93,63.63 75.93,64.52 76.06,64.64 76.32,64.64 76.44,64.52 76.44,63.5 76.57,63.37 76.82,63.37 76.95,63.5 76.95,64.52 77.08,64.64 77.33,64.64 77.46,64.52 77.46,63.5 77.59,63.37 77.84,63.37 77.97,63.5 77.97,64.52 78.09,64.64 78.35,64.64 78.47,64.52 78.47,63.5 78.6,63.37 78.86,63.37 78.98,63.5 78.98,64.52 79.11,64.64 79.36,64.64 79.49,64.52 79.49,63.5 79.62,63.37 79.87,63.37 80,63.5 80,64.52 80.13,64.64 84.58,64.64 86.11,63.12 v1(86.11,62.74) ; v1(87.12,59.31) 88.39,58.04 88.77,58.04 89,57.81 SW8.4
GPIO_EMC_17: length 41.4
  TOP w0.127: R300.2 72.19,57.4 v1(72.26,57.48) ; v1(86.23,59.31) 85.85,59.69 U14.24 85.85,62.1 v1(85.22,62.74)
  BOTTOM w0.127: v1(86.23,59.31) 87.63,57.91 R253.2 SW8.3 ; v1(72.26,57.48) 72.47,57.48 74.68,59.69 80.14,59.69 80.26,59.82 80.26,60.56 80.14,60.69 76.96,60.69 76.83,60.81 76.83,61.07 76.96,61.19 80.14,61.19 80.26,61.32 80.26,61.57 80.14,61.7 76.96,61.7 76.83,61.83 76.83,62.08 76.96,62.21 79.99,62.21 81.53,63.75 84.2,63.75 v1(85.22,62.74)
GPIO_EMC_18: length 45.1
  TOP w0.127: v1(74.55,57.91) 74.42,57.78 R301.2 ; v1(85.34,59.31) 85.05,59.6 U14.25 85.05,62.14 v1(84.45,62.74)
  BOTTOM w0.127: v1(84.45,62.74) 83.82,63.37 82.04,63.37 81.92,63.25 81.92,58.04 81.79,57.91 81.56,57.91 81.44,58.04 81.44,58.8 81.31,58.93 81.05,58.93 80.93,58.8 80.93,58.04 80.8,57.91 80.55,57.91 80.42,58.04 80.42,58.8 80.29,58.93 80.04,58.93 79.91,58.8 79.91,58.04 79.78,57.91 79.53,57.91 79.4,58.04 79.4,58.8 79.28,58.93 79.02,58.93 78.9,58.8 78.9,58.04 78.77,57.91 78.51,57.91 78.39,58.04 78.39,58.8 78.26,58.93 78.01,58.93 77.88,58.8 77.88,58.04 77.75,57.91 77.5,57.91 77.37,58.04 77.37,58.8 77.24,58.93 76.99,58.93 76.86,58.8 76.86,58.04 76.74,57.91 76.48,57.91 76.36,58.04 76.36,58.8 76.23,58.93 75.97,58.93 75.85,58.8 75.85,58.04 75.72,57.91 75.47,57.91 75.34,58.04 75.34,58.8 75.21,58.93 74.96,58.93 74.83,58.8 74.83,58.04 74.7,57.91 v1(74.55,57.91) ; v1(85.34,59.31) 85.85,59.82 88.9,59.82 89.41,59.31 89.41,58.8 90.04,58.17 90.04,58.04 90.42,57.66 90.42,52.83 90.04,52.45 SW8.1
GPIO_EMC_19: length 33.9
  TOP w0.127: R302.2 v1(74.55,56.77) ; U14.26 84.25,62.18 v1(83.69,62.74) 83.19,62.74 82.68,62.23 R263.2
  BOTTOM w0.127: v1(74.55,56.77) 82.93,56.77 83.19,57.02 83.19,58.27 83.31,58.4 84.2,58.4 84.33,58.52 84.33,58.78 84.2,58.9 83.31,58.9 83.19,59.03 83.19,59.41 83.31,59.54 84.2,59.54 84.33,59.67 84.33,59.92 84.2,60.05 83.31,60.05 83.19,60.17 83.19,60.56 83.31,60.68 86.23,60.68 86.36,60.81 86.36,61.06 86.23,61.19 83.31,61.19 83.19,61.32 83.19,61.57 83.31,61.7 85.22,61.7 85.34,61.83 85.34,62.08 85.22,62.21 83.31,62.21 83.19,62.33 83.19,62.61 83.31,62.74 v1(83.69,62.74)
GPIO_EMC_20: length 32.5
  TOP w0.127: v1(84.07,51.05) 84.25,50.87 U14.29 ; R303.2 v1(74.55,55.75)
  BOTTOM w0.127: R262.2 v1(84.07,51.05) 84.07,51.59 83.95,51.72 83.31,51.72 83.19,51.85 83.19,52.1 83.31,52.23 85.09,52.23 85.22,52.36 85.22,52.61 85.09,52.74 83.31,52.74 83.19,52.86 83.19,53.12 83.31,53.24 85.09,53.24 85.22,53.37 85.22,53.63 85.09,53.75 83.31,53.75 83.19,53.88 83.19,54.13 83.31,54.26 85.09,54.26 85.22,54.39 85.22,54.64 85.09,54.77 83.31,54.77 83.19,54.9 83.19,55.15 83.31,55.28 85.09,55.28 85.22,55.4 85.22,55.63 85.09,55.75 v1(74.55,55.75)
GPIO_EMC_21: length 31.6
  TOP w0.127: U14.30 85.05,48.22 84.84,48.01 82.55,48.01 v1(82.42,48.13) ; R288.2 v1(74.55,54.74)
  BOTTOM w0.127: v1(74.55,54.74) 77.72,54.74 77.84,54.61 77.84,54.23 77.97,54.1 78.22,54.1 78.35,54.23 78.35,54.61 78.48,54.74 78.73,54.74 78.86,54.61 78.86,53.85 78.99,53.72 79.24,53.72 79.37,53.85 79.37,54.61 79.49,54.74 79.75,54.74 79.87,54.61 79.87,53.85 80,53.72 80.26,53.72 80.38,53.85 80.38,54.61 80.51,54.74 80.77,54.74 80.9,54.61 80.9,53.34 81.03,53.21 81.79,53.21 81.92,53.09 81.92,52.83 81.78,52.7 80.26,52.7 80.14,52.57 80.14,52.32 80.26,52.19 81.79,52.19 81.92,52.07 81.92,51.81 81.79,51.69 80.26,51.69 80.14,51.56 80.14,51.3 80.26,51.18 81.79,51.18 81.92,51.05 81.92,50.8 81.79,50.67 81.03,50.67 80.9,50.55 80.9,49.28 81.03,49.15 82.3,49.15 R261.2 v1(82.42,48.13)
GPIO_EMC_22: length 32.1
  TOP w0.127: U14.31 85.85,48.13 v1(85.6,47.88) ; R289.2 v1(74.55,53.72)
  BOTTOM w0.127: v1(85.6,47.88) 85.85,48.13 R271.2 R260.2 84.58,48.64 84.58,48.39 84.07,47.88 84.07,46.1 83.95,45.97 82.95,45.97 82.82,46.1 82.82,46.99 82.7,47.12 82.44,47.12 82.32,46.99 82.32,46.1 82.19,45.97 81.92,45.97 81.79,46.1 81.79,46.99 81.66,47.12 81.42,47.12 81.29,46.99 81.29,46.1 81.16,45.97 80.91,45.97 80.78,46.1 80.78,46.99 80.53,47.24 79.5,47.24 79.25,47.5 79.25,47.68 79.38,47.8 80.01,47.8 80.14,47.93 80.14,48.19 80.01,48.31 79.38,48.31 79.25,48.44 79.25,48.69 79.38,48.82 80.01,48.82 80.14,48.95 80.14,49.2 80.01,49.33 79.38,49.33 79.25,49.46 79.25,49.71 79.38,49.84 80.01,49.84 80.14,49.96 80.14,50.22 80.01,50.34 79.38,50.34 79.25,50.47 79.25,51.82 77.22,53.85 74.68,53.85 v1(74.55,53.72)
GPIO_EMC_23: length 41.2
  TOP w0.127: v1(86.49,47.88) 86.65,48.05 U14.32 ; R290.2 v1(72.14,52.83)
  BOTTOM w0.127: v1(72.14,52.83) 72.44,53.14 76.78,53.14 78.49,51.44 78.49,47.24 79.33,46.4 79.73,46.4 79.86,46.28 79.86,46.02 79.73,45.9 78.87,45.9 78.74,45.77 78.74,45.51 78.87,45.39 79.76,45.39 79.88,45.26 79.88,45.01 79.76,44.88 78.87,44.88 78.74,44.75 78.74,44.45 78.87,44.32 80.91,44.32 81.03,44.45 81.03,45.09 81.16,45.21 81.41,45.21 81.54,45.09 81.54,44.45 81.67,44.32 82.37,44.32 82.5,44.45 82.5,45.09 82.62,45.21 82.88,45.21 83.01,45.09 83.01,44.45 83.13,44.32 85.47,44.32 85.6,44.45 85.6,45.34 85.98,45.72 85.98,47.37 v1(86.49,47.88) 86.49,51.82 87.38,52.7 87.63,52.7 88.65,53.72 SW8.2
GPIO_EMC_24: length 36.4
  TOP w0.127: U14.33 87.45,48.08 v1(87.25,47.88) ; R295.2 v1(72.14,51.94)
  BOTTOM w0.127: v1(72.14,51.94) 72.62,51.94 72.77,52.1 72.77,52.58 72.97,52.78 76.5,52.78 77.98,51.31 77.98,43.36 78.41,42.93 78.62,42.93 78.74,42.8 78.74,42.55 78.87,42.42 79.12,42.42 79.25,42.55 79.25,43.43 79.38,43.56 79.63,43.56 79.76,43.43 79.76,42.55 79.89,42.42 80.14,42.42 80.27,42.55 80.27,42.8 80.39,42.93 80.62,42.93 80.75,42.8 80.75,42.55 80.88,42.42 81.13,42.42 81.26,42.55 81.26,42.8 81.38,42.93 84.96,42.93 85.6,43.56 86.36,43.56 86.87,44.07 86.87,45.34 87,45.47 87,47.62 v1(87.25,47.88) 87.12,48.01 R258.2 R315.2
GPIO_EMC_25: length 33.7
  TOP w0.127: R294.2 v1(74.55,51.94) ; v1(88.04,47.88) 88.2,48.04 88.2,49.4 U14.34
  BOTTOM w0.127: R257.2 R314.2 88.04,48.16 v1(88.04,47.88) 87.88,47.73 87.88,43.94 87.63,43.69 87.63,42.67 87.2,42.24 81.99,42.24 81.41,41.66 78.61,41.66 77.09,43.18 77.09,43.94 76.96,44.07 76.96,48.46 76.83,48.59 76.58,48.59 76.45,48.72 76.45,48.97 76.58,49.1 76.83,49.1 76.96,49.23 76.96,49.48 76.83,49.61 76.58,49.61 76.45,49.73 76.45,49.98 76.58,50.1 76.83,50.1 76.96,50.23 76.96,50.48 76.83,50.61 76.58,50.61 76.45,50.74 76.45,51.18 75.69,51.94 v1(74.55,51.94)
GPIO_EMC_26: length 35
  TOP w0.127: R296.2 v1(74.55,50.93) ; U14.35 89.05,47.9 v1(89.03,47.88)
  BOTTOM w0.127: v1(74.55,50.93) 75.18,50.93 75.51,50.6 75.51,45.96 75.82,45.65 75.82,43.31 78.23,40.89 82.19,40.89 82.32,41.02 82.32,41.4 82.44,41.53 82.7,41.53 82.82,41.4 82.82,41.02 82.95,40.89 83.21,40.89 83.33,41.02 83.33,41.4 83.46,41.53 87.76,41.53 88.9,42.67 88.9,47.75 v1(89.03,47.88) 89.53,48.39 89.96,48.39 90.6,49.02 R256.2 R270.2
GPIO_EMC_27: length 35.5
  TOP w0.127: U14.36 89.85,47.94 v1(89.79,47.88) ; v1(74.55,49.78) R298.2
  BOTTOM w0.127: R255.2 R269.2 91.82,48.39 90.39,48.39 89.89,47.88 v1(89.79,47.88) 90.04,47.62 90.04,42.29 88.27,40.51 77.98,40.51 74.55,43.94 v1(74.55,49.78)
GPIO_SD_B1_02: length 149.7
  TOP w0.127: v1(54.48,82.3) R251.2 55.12,82.16 R249.2 54.61,80.64 54.61,64.01 TP11.1 52.16,61.56 U1.30 ; v1(69.09,78.23) 76.37,78.23 76.88,78.74 93.43,78.74 94.74,77.43 94.74,75.14 106.17,63.71 106.17,47.24 v1(95.76,36.83) ; v1(95.76,33.15) 96.39,32.51 123.3,32.51 R174.2
  BOTTOM w0.127: v1(54.48,82.3) 56.77,80.01 63.5,80.01 65.28,78.23 v1(69.09,78.23) ; v1(95.76,33.15) v1(95.76,36.83)
GPIO_SD_B1_03: length 139.9
  TOP w0.127: v1(94.74,33.15) 95.89,32 121.27,32 R173.2 ; v1(68.45,77.22) 76.07,77.22 77.09,78.23 93.22,78.23 94.23,77.22 94.23,74.93 105.66,63.5 105.66,48.51 94.74,37.59 v1(94.74,36.83) ; U1.28 53.16,60.4 53.21,60.45 53.21,61.85 53.98,62.61 54.36,62.61 55.37,63.63 TP12.1 54.99,65.15 54.99,75.31 57.4,77.72 R250.2 59.06,77.86 R252.2 v1(60.07,77.22)
  BOTTOM w0.127: v1(60.07,77.22) 60.58,76.71 63.88,76.71 64.39,77.22 v1(68.45,77.22) ; v1(94.74,33.15) v1(94.74,36.83)
HP_JD: length 38.2
  TOP w0.305: U10.7 v1(60.6,28.05)
  TOP w0.381: v1(64.64,16.64) 64.64,18.29 v1(61.21,21.72) ; v1(58.17,9.91) R84.2 R81.2 58.17,7.21 TVS3.2 49.55,6.73 J11.5
  BOTTOM w0.381: v1(60.6,28.05) 60.6,22.33 v1(61.21,21.72) ; v1(58.17,9.91) 58.17,10.17 v1(64.64,16.64)
HP_L: length 2.2
  TOP w0.305: C102.1 57.78,23.62 57.77,23.62 U10.31
HP_MIC1N: length 5.9
  TOP w0.107: C112.1 63.37,25.02 63,25.02 C110.2 62.48,25.02 62.05,25.02 60.9,26.18 59.63,26.18 59.53,26.28 59.53,26.44 59.42,26.55 U10.4
HP_MIC1P: length 6
  TOP w0.107: C115.1 63.4,24.76 62.99,24.76 C116.1 62.48,24.77 61.94,24.77 60.79,25.92 59.63,25.92 59.53,25.81 59.53,25.65 59.42,25.55 U10.2
HP_R: length 2
  TOP w0.305: U10.29 56.77,23.75 57.28,23.24 C103.1
INT1_COMBO: length 55.3
  TOP w0.127: v1(50.8,49.78) 50.8,56.51 51.84,57.56 53.11,57.56 53.66,58.11 U1.27 53.66,61.41 56.13,63.88 56.13,65.28 55.37,66.04 55.37,75.09 57.02,76.73 62.76,76.73 63.3,77.27 66.6,77.27 68.45,79.12 68.45,84.07 68.07,84.45 R241.2 R242.2
  BOTTOM w0.127: v1(50.8,49.78) R316.1
INT2_COMBO: length 35.4
  TOP w0.127: U1.26 54.16,60.39 53.97,60.59 53.97,61.21 56.52,63.75 56.52,65.53 55.75,66.29 55.75,74.93 57.25,76.43 62.9,76.43 63.43,76.96 67.06,76.96 69.09,78.99 v1(69.09,79.38) ; R243.2 R240.2 v1(67.94,79.38)
  BOTTOM w0.127: v1(67.94,79.38) v1(69.09,79.38)
JTAG_DACK: length 4.5
  TOP w0.127: J16.19 R152.1
JTAG_DE: length 4.5
  TOP w0.127: R144.2 J16.17
JTAG_MOD: length 3.1
  TOP w0.127: R57.1 71.49,39.89 U1.109
JTAG_NSRST: length 6.2
  TOP w0.127: J16.15 113.28,45.84 R145.2 113.54,46.11 D13.C
JTAG_RTCK: length 4.5
  TOP w0.127: R151.1 J16.11
JTAG_TCK: length 82.7
  TOP w0.127: J16.9 R150.1 v1(121.67,45.47) 121.67,46.48 118.62,49.53 109.86,49.53 96.01,35.69 91.44,35.69 88.65,32.89 85.22,32.89 81.53,36.58 76.71,36.58 72.89,40.39 U1.110 ; v1(122.56,46.23) 126.11,49.78 v1(126.11,51.69)
  BOTTOM w0.127: v1(122.56,46.23) 122.43,46.23 121.67,45.47 v1(121.67,45.47) ; v1(126.11,51.69) J28.2
JTAG_TDI: length 164.4
  TOP w0.127: J16.5 124.71,39.75 124.71,36.32 123.7,35.31 123.7,34.42 R147.2 104.27,34.42 103.38,35.31 91.69,35.31 88.77,32.38 85.09,32.38 81.28,36.2 76.53,36.2 75.9,36.83 74.93,36.83 72.77,38.99 69.98,38.99 v1(68.45,37.47) 68.33,37.34 66.79,37.34 66.66,37.47 U1.108 ; C61.1 25.27,41.78 34.29,41.78 40.01,36.07 v1(40.01,34.04) ; v1(70.99,27.3) 71.17,27.3 72.39,26.09 72.39,14.86 70.1,12.57 67.31,12.57 62.61,17.27 54.61,17.27 54.36,17.53 44.7,17.53 44.2,18.03 44.2,21.64 40.01,25.83 v1(40.01,26.8)
  BOTTOM w0.127: v1(70.99,27.3) 70.99,34.92 v1(68.45,37.47) ; v1(40.01,34.04) v1(40.01,26.8)
JTAG_TMS: length 86.5
  TOP w0.127: v1(126.62,54.61) 126.62,49.66 125.35,48.39 125.35,46.99 123.83,45.47 R146.2 ; U1.111 73.03,40.89 76.84,37.08 81.67,37.08 85.34,33.4 88.52,33.4 91.31,36.2 95.89,36.2 109.6,49.91 118.87,49.91 122.05,46.74 122.05,45.97 122.55,45.47 R146.2 ; R146.2 J16.7
  BOTTOM w0.127: J27.2 128.4,54.61 v1(126.62,54.61)
JTAG_VREF: length 4.5
  TOP w0.127: R149.2 J16.1
MAIN_MIC2N: length 14
  TOP w0.107: U10.5 59.42,27.05 59.54,27.17 61.08,27.17 62.22,28.32 65.1,28.32 65.22,28.19 65.52,28.19 65.65,28.32 65.86,28.32 65.98,28.19 66.23,28.19 66.35,28.32 66.66,28.32 66.78,28.19 67.08,28.19 67.21,28.32 67.51,28.32 67.63,28.19 67.94,28.19 68.06,28.32 68.33,28.32 69.15,27.5 69.15,26.86 C119.1 69.15,26.22 69.15,25.71 C114.2
MAIN_MIC2P: length 14
  TOP w0.107: U10.6 59.42,27.55 59.54,27.43 60.97,27.43 62.12,28.57 68.44,28.57 69.41,27.61 69.41,26.86 C107.2 69.41,26.22 69.41,25.71 C111.2
MCU_DCDC_IN: length 41.2
  TOP w0.305: R33.1 45.72,57.66 45.72,57.51 46.33,56.89 U1.38 ; 50.16,60.58 U1.34
  TOP w0.381: C31.1 49.8,63.61 49.15,64.26 48.26,64.26 45.97,66.55 42.48,66.55 39.33,69.7 35.08,69.7 34.29,70.48 34.29,75.56 R357.1 33.53,76.33 J37.1 ; R33.1 44.96,58.17 43.94,59.19 C35.1 v1(42.93,59.19)
  BOTTOM w0.381: v1(42.93,59.19) 43.05,59.31 47.75,59.31 v1(49.91,61.47)
MCU_DCDC_IN_3V3: length 28.5
  TOP w0.381: J37.2 36.07,76.33 R357.2 35.56,75.18 34.92,74.55 34.92,70.69 35.36,70.26 39.56,70.26 42.69,67.13 46.28,67.13 48.51,64.9 49.78,64.9 50.16,64.52 C55.1 50.93,64.65 R47.2 R44.2
MICBIAS: length 19.9
  TOP w0.127: R94.1 61.73,26.93 61.47,26.67 v1(59.94,26.67) ; v1(70.99,22.23) 71.75,22.23 R95.1 ; U10.1 v1(59.94,25.05) 59.98,25.01 C98.1 60.97,25.01 62.1,23.88 62.1,23.11 63.88,21.34 67.06,21.34 v1(67.94,22.23)
  BOTTOM w0.127: v1(59.94,25.05) v1(59.94,26.67) ; v1(70.99,22.23) v1(67.94,22.23)
NVCC_GPIO_3V3: length 23.5
  TOP w0.305: U1.29 52.66,58.21 v1(52.83,58.04) ; v1(64.9,39.37) 64.66,39.14 U1.104 ; U1.112 67.43,41.39 v1(67.18,41.15) ; U1.11 61.66,58.23 v1(61.47,58.04) ; v1(67.18,57.15) 67.42,57.39 U1.144 ; U1.20 57.16,58.3 v1(56.9,58.04) ; U1.77 v1(51.16,39.24)
  BOTTOM w0.381: v1(64.9,39.37) 65.15,39.62 C67.1 v1(65.15,41.02) C74.1 67.06,41.02 v1(67.18,41.15) 67.94,41.15 C176.1 ; C178.1 56.9,58.05 v1(56.9,58.04) C69.1 v1(56.9,56.26) ; v1(66.29,56.26) 66.29,57.02 66.42,57.15 v1(67.18,57.15) ; v1(61.47,56.26) C72.1 v1(61.47,58.04) 61.35,58.16 C177.1 ; v1(52.83,58.04) 52.83,57.78 C73.1 53.09,57.02 v1(52.58,57.02)
  vias: v1(46.35,33.91) v1(47.37,33.91) v1(48.26,34.8) v1(48.26,33.91) v1(48.26,33.02) v1(51.31,41.53) v1(51.31,40.77) v1(52.07,41.53) v1(52.07,40.77)
NVCC_SD: length 29.5
  TOP w0.381: v1(32.64,64.14) 32.64,61.21 33.22,60.63 33.22,57.4 35.56,55.07 v1(39.32,55.07) 39.62,55.37 R60.1 ; R58.1 R59.1 43.47,53.33 v1(43.49,53.36)
  BOTTOM w0.381: v1(39.32,55.07) 41.76,55.07 43.47,53.36 v1(43.49,53.36) ; v1(32.64,64.14) 32,64.77 v1(25.02,64.77)
ONOFF: length 62.9
  TOP w0.127: v1(12.19,56.9) 8.89,60.2 C172.1 7.2,69.63 SW2.3 SW2.4 ; v1(20.07,55.75) 20.19,55.63 20.95,55.63 24.13,52.45 31.7,52.45 32.21,52.96 32.77,52.96 33.22,52.5 35.38,52.5 36.32,51.56 38.48,51.56 38.99,51.05 43.31,51.05 44.07,51.82 45.47,51.82 45.89,51.39 U1.49
  BOTTOM w0.127: v1(20.07,55.75) 18.92,56.9 v1(12.19,56.9)
OTG1_DN: length 36.4
  TOP w0.119: U1.62 46.35,44.89 46.22,44.76 45.94,44.76 45.5,44.32 43.81,44.32 42.82,43.32 36.69,43.32 35.94,44.07 13.29,44.07 13.02,44.34 L4.1 12.04,44.34 R61.2
OTG1_DP: length 36.4
  TOP w0.119: U1.63 46.35,44.39 46.22,44.52 46.04,44.52 45.6,44.08 43.92,44.08 42.92,43.08 36.58,43.08 35.84,43.82 13.29,43.82 13.02,43.54 L4.4 12.04,43.54 R63.2
PMIC_ON_REQ: length 48.1
  TOP w0.127: v1(42.29,42.16) 42.16,42.04 36.07,42.04 35.31,42.8 20.07,42.8 15.75,38.48 15.75,33.78 17.14,32.39 R43.2 R41.2 ; v1(48.39,49.28) 48.27,49.39 U1.53
  BOTTOM w0.127: v1(48.39,49.28) 48.01,48.9 48.01,47.88 v1(42.29,42.16)
POR_B: length 212.5
  TOP w0.127: U1.50 45.88,50.89 45.34,51.44 44.2,51.44 43.43,50.67 38.86,50.67 38.28,51.26 36.12,51.26 35.18,52.2 32.64,52.2 v1(32.38,52.45) ; U15.7 R179.2 118.24,66.42 J21.1 ; J21.1 111.12,68.58 111.12,70.99 108.46,73.66 108.46,77.34 103.76,82.04 103.76,85.85 101.35,88.27 v1(66.55,88.27) ; J21.1 113.27,66.41 D15.C 113.27,59.96 J22.3 114.81,58.42 v1(115.06,58.42) R191.2 ; v1(11.81,61.47) 11.81,80.14 19.68,88.01 v1(42.16,88.01) ; v1(114.51,48.9) 114.48,48.86 D13.A ; v1(114.51,50.76) 115.82,52.07 v1(115.82,55.88) ; D8.C 22.26,61.43 v1(22.48,61.21) 23.37,60.33 27.81,60.33 29.34,58.8 29.34,55.88 C28.1 R22.2 R26.2 31.58,54.35 v1(31.62,54.31)
  BOTTOM w0.127: v1(11.81,61.47) 12.19,61.09 22.35,61.09 v1(22.48,61.21) ; v1(115.82,55.88) 115.32,56.39 115.32,58.17 v1(115.06,58.42) ; v1(31.62,54.31) 32.38,53.54 v1(32.38,52.45) ; v1(114.51,48.9) v1(114.51,50.76) ; v1(66.55,88.27) 65.91,88.9 43.05,88.9 v1(42.16,88.01)
POR_BUTTON: length 31.6
  TOP w0.127: v1(19.3,39.5) 20.45,40.64 R50.1 ; v1(9.53,37.97) C173.1 7.2,36.41 SW3.4 SW3.3 ; v1(16.26,37.97) 16.26,34.04 17.15,33.14 R43.1
  BOTTOM w0.127: v1(9.53,37.97) v1(16.26,37.97) 17.78,37.97 v1(19.3,39.5)
POWER_EN: length 8.6
  TOP w0.127: U16.31 125.84,77.32 128.14,79.63 130.94,79.63 131.32,79.25 R214.1
SAI1_MCLK: length 5.6
  TOP w0.127: U1.92 58.66,35.32 59.56,34.42 R90.1
SAI1_RXD: length 6.6
  TOP w0.127: R88.1 54.48,33.31 54.61,33.43 54.86,33.43 54.99,33.56 54.99,33.81 54.86,33.94 54.61,33.94 54.48,34.07 54.48,34.42 55.37,35.31 55.37,35.81 56.16,36.6 U1.87
SAI1_TX_BCLK: length 6.1
  TOP w0.127: R87.1 58.55,33.44 58.67,33.57 58.93,33.57 59.05,33.7 59.05,33.95 58.93,34.08 58.67,34.08 58.55,34.21 58.55,34.54 58.16,34.93 U1.91
SAI1_TX_SYNC: length 6.1
  TOP w0.127: U1.90 57.66,34.55 57.53,34.42 57.53,34.14 57.66,34.01 57.99,34.01 58.12,33.89 58.12,33.63 57.99,33.51 57.66,33.51 57.53,33.38 R85.1
SAI1_TXD: length 6.4
  TOP w0.127: R89.1 56.52,33.36 56.64,33.49 56.9,33.49 57.02,33.62 57.02,33.87 56.9,34 56.64,34 56.52,34.13 56.52,34.42 56.64,34.54 57.03,34.54 57.16,34.67 U1.89
SD1_CLK: length 7.7
  TOP w0.127: R138.1 C140.1 40.89,53.85 43.69,53.85 44.14,53.39 U1.45
SD1_CMD: length 24
  TOP w0.127: R362.1 30.61,60.33 31.47,59.46 31.47,56.67 34.42,53.72 36.53,53.72 37.67,52.58 38.84,52.58 39.32,52.1 42.31,52.1 R59.2 43.31,52.58 43.62,52.89 U1.46
SD1_D0: length 25.1
  TOP w0.127: R58.2 v1(41.02,52.58) ; R363.1 33.66,61.98 33.66,57.66 35.15,56.16 42.77,56.16 v1(44.45,54.48) 44.54,54.39 U1.43
  BOTTOM w0.127: v1(44.45,54.48) 44.45,53.59 43.69,52.83 41.27,52.83 v1(41.02,52.58)
SD1_D1: length 24.1
  TOP w0.127: U1.42 45.82,54.89 45.72,54.99 44.45,54.99 42.98,56.46 35.36,56.46 33.96,57.86 33.96,64.59 33.15,65.41 R364.1
SD1_D2: length 25.7
  TOP w0.127: R360.1 28.57,61.09 30.86,58.8 30.86,56.42 34.17,53.11 36.27,53.11 37.49,51.89 38.66,51.89 39.12,51.44 43.18,51.44 43.94,52.2 45.72,52.2 46.03,51.89 U1.48
SD1_D3: length 26.9
  TOP w0.127: U1.47 46.16,52.39 46.03,52.52 43.76,52.52 43,51.77 39.22,51.77 38.79,52.2 37.62,52.2 36.4,53.42 34.29,53.42 31.16,56.55 31.16,59.13 29.59,60.71 R361.1
SD_CD_SW: length 34.5
  TOP w0.127: v1(33.91,65.53) 34.26,65.18 34.26,58.06 35.56,56.77 43.18,56.77 44.56,55.39 U1.41 ; J15.9 24.77,68.84 R139.2 R141.1 25.66,68.32 v1(27.3,66.67)
  BOTTOM w0.127: v1(27.3,66.67) 29.84,66.67 30.61,65.91 33.53,65.91 v1(33.91,65.53)
SD_PWREN: length 35.6
  TOP w0.127: D7.C 20.03,61.43 19.05,60.45 19.05,54.99 19.94,54.1 20.83,54.1 23.37,51.56 34.8,51.56 35.72,50.64 37.88,50.64 38.61,49.91 44.45,49.91 v1(44.58,49.78)
  BOTTOM w0.127: R316.2 v1(44.58,49.78)
SDA_EXTAL: length 5.8
  TOP w0.127: Y3.3 118.43,72.45 C161.1 119.25,71.63 119.76,71.63 121.18,73.05 U16.17
SDA_JTAG_TCLK: length 14.5
  TOP w0.127: U16.12 119.38,76.32 110.49,85.22 J29.4
SDA_JTAG_TDI: length 13.6
  TOP w0.127: U16.13 119.25,75.82 112.39,82.68 J29.8
SDA_JTAG_TDO: length 14.4
  TOP w0.127: U16.14 119.24,75.32 112.39,82.17 v1(112.14,82.17)
  BOTTOM w0.127: 109.73,83.95 110.36,83.95 v1(112.14,82.17)
SDA_JTAG_TMS: length 18.4
  TOP w0.127: v1(112.9,80.9) 113.16,80.9 119.23,74.82 U16.15 ; J29.2 R207.2 112.02,84.32 v1(112.9,83.44)
  BOTTOM w0.127: v1(112.9,83.44) v1(112.9,80.9)
SDA_LED: length 2.6
  TOP w0.127: U16.29 126.86,76.32 D16.C
SDA_LED_R: length 1.4
  TOP w0.127: R198.2 129.16,77.08 D16.A
SDA_RST: length 28.1
  TOP w0.127: U16.19 122.19,71.77 119.89,69.47 R196.1 119.88,68.45 R195.2 118.62,68.2 TP24.1 116.33,68.2 115.06,69.47 115.06,73.41 116.2,74.55 116.2,77.22 113.03,80.39 110.74,80.39 J29.10
SDA_RST_LED: length 1.1
  TOP w0.127: D15.A R186.2
SDA_RST_TGTMCU_B: length 20.6
  TOP w0.127: v1(122.94,70.23) 123.19,70.48 U16.21 ; v1(122.94,67.56) 122.94,58.55 J24.1
  BOTTOM w0.127: v1(122.94,70.23) 123.19,69.98 123.19,67.82 v1(122.94,67.56)
SDA_RST_TGTMCU_J_B: length 3.7
  TOP w0.127: R191.1 R188.1 J24.2
SDA_RX_EN: length 3.2
  TOP w0.127: R193.1 135.13,62.87 R194.2 135.13,65.15 135.38,65.41 U21.5
SDA_SPI0_CS: length 2.8
  TOP w0.127: U16.23 124.19,72.16 TP23.1
SDA_SPI0_RST_B: length 4.8
  TOP w0.127: U16.22 123.69,70.88 TP22.1
SDA_SPI0_SCK: length 33.2
  TOP w0.127: U24.3 137,51.66 138.94,53.59 138.94,66.42 136.02,69.34 131.32,69.34 125.84,74.82 U16.26
SDA_SPI0_SIN: length 25.4
  TOP w0.127: U16.28 v1(126.24,75.82) ; U22.3 136.83,60.37 137.79,61.34 137.79,65.79 135.38,68.2 130.18,68.2 126.24,72.14 v1(126.24,72.9)
  BOTTOM w0.127: v1(126.24,72.9) 126.75,73.41 126.75,75.31 126.24,75.82 v1(126.24,75.82)
SDA_SPI0_SOUT: length 28.8
  TOP w0.127: v1(126.24,73.66) 130.94,68.96 135.76,68.96 138.56,66.17 138.56,57.91 137,56.36 U23.3 ; U16.27 125.97,75.32 v1(126.24,75.06)
  BOTTOM w0.127: v1(126.24,73.66) v1(126.24,75.06)
SDA_SWD_EN: length 29.4
  TOP w0.127: U17.6 v1(123.67,70.2) ; v1(123.7,67.56) 123.7,66.8 126.11,64.39 126.11,60.83 128.02,58.93 128.02,51.82 131.18,48.65 R204.1
  BOTTOM w0.127: v1(123.67,70.2) 123.67,67.59 v1(123.7,67.56)
SDA_SWD_EN_B: length 1.7
  TOP w0.127: U16.16 119.4,74.32 R184.2
SDA_SWD_EN_B_R: length 15.1
  TOP w0.127: R184.1 R182.2 117.47,73.41 117.21,73.15 115.57,73.15 115.44,73.03 115.44,69.72 115.95,69.22 v1(117.35,69.22) ; U17.1 122.44,69.33 v1(122.17,69.6)
  BOTTOM w0.127: v1(122.17,69.6) 121.79,69.98 118.11,69.98 v1(117.35,69.22)
SDA_SWD_EN_R: length 4.6
  TOP w0.127: R206.2 136.9,49.4 R205.1 R204.2 135,51.05 135.25,51.31 U24.5
SDA_SWD_OE: length 22.4
  TOP w0.127: U17.4 123.82,68.33 124.33,67.82 124.33,66.8 126.62,64.52 126.62,60.96 128.52,59.05 128.52,55.24 130.42,53.35 R199.1
SDA_SWD_OE_B: length 4.2
  TOP w0.127: U16.20 122.69,71.24 R187.2
SDA_SWD_OE_B_R: length 2.4
  TOP w0.127: R187.1 R185.2 121.53,68.33 U17.3
SDA_SWD_OE_R: length 4.6
  TOP w0.127: U23.5 135.25,56.01 135,55.75 R199.2 R201.1 136.9,54.1 R202.2
SDA_USB_CONN_DN: length 4.6
  TOP w0.119: J23.2 123.84,85.05 123.64,84.85 123.64,83.99 U20.1 123.63,82.62 123.63,82.36 R189.1
